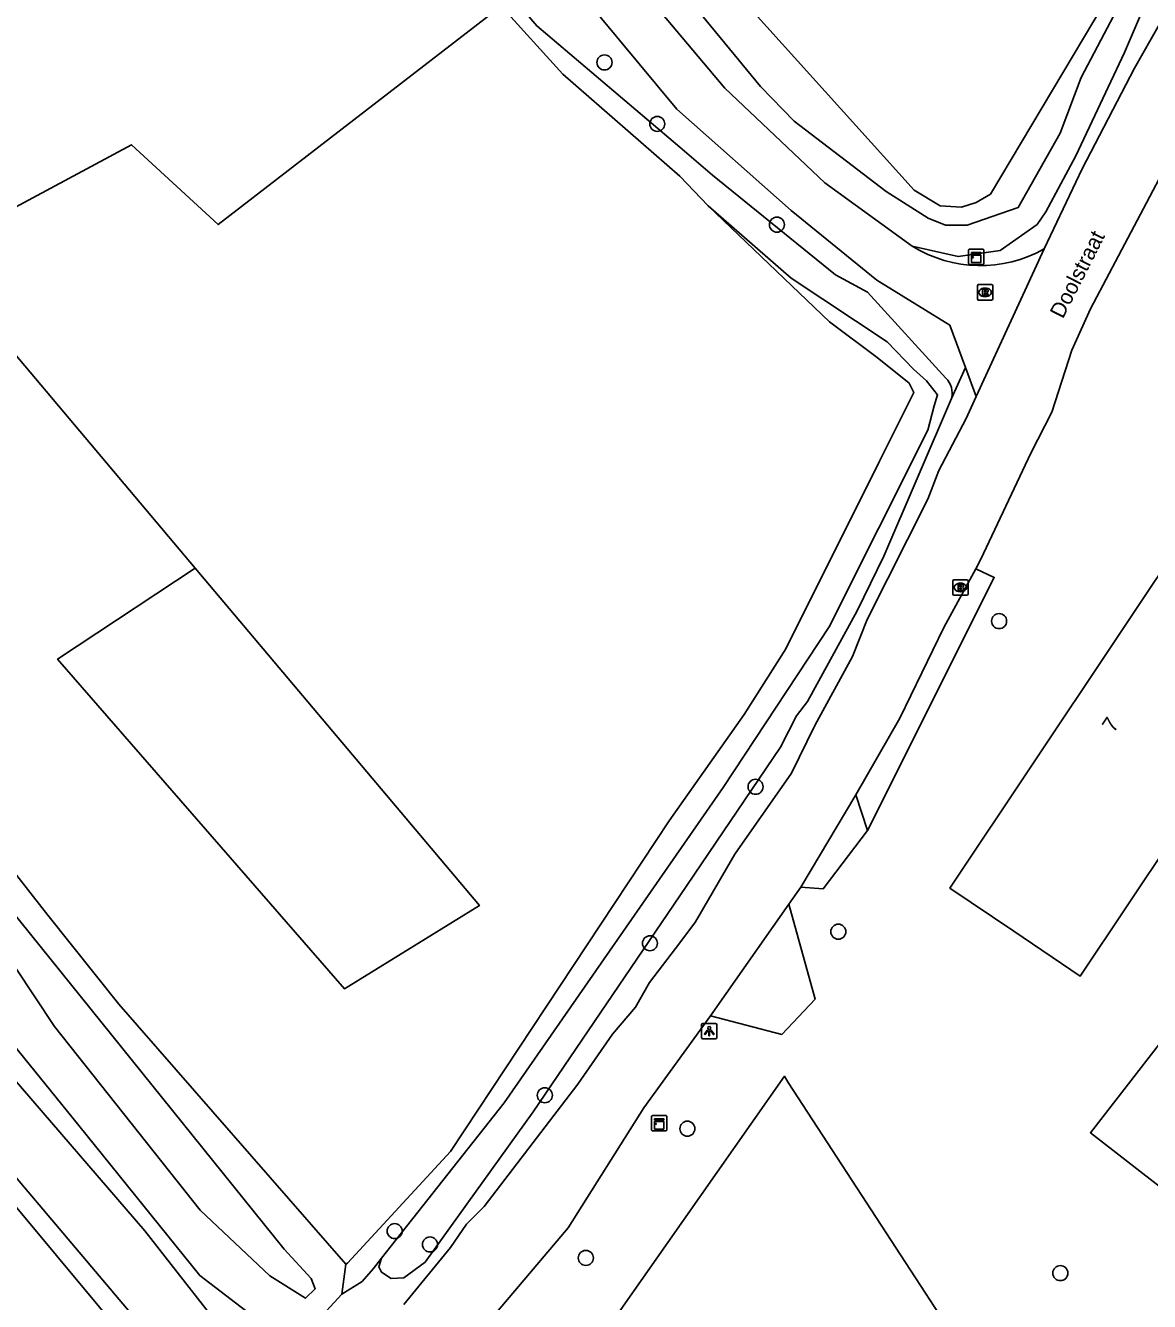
# Model space of a CAD drawing. Extents: x 164494 to 166241, y 382475 to 384494.
# Drawn here: x 164957.5 to 165030.5, y 382904.2 to 382987.1 of the extents above; entities that cross this region are included whole.
import ezdxf

# ---------------------------------------------------------------- set-up
doc = ezdxf.new("R2010")
doc.units = 0
for name, color, linetype in [('IMGEO_Boom', 7, 'Continuous'), ('IMGEO_Brandkraan', 7, 'Continuous'), ('IMGEO_Grasland_agrarisch', 7, 'Continuous'), ('IMGEO_Grasland_overig', 7, 'Continuous'), ('IMGEO_Groenvoorziening', 7, 'Continuous'), ('IMGEO_Hek', 7, 'Continuous'), ('IMGEO_Kast', 7, 'Continuous'), ('IMGEO_Lichtpunt', 7, 'Continuous'), ('IMGEO_Loofbos', 7, 'Continuous'), ('IMGEO_Openbare_ruimte_label', 7, 'Continuous'), ('IMGEO_Pand', 7, 'Continuous'), ('IMGEO_Pand_nummerreeks', 7, 'Continuous'), ('IMGEO_Rijbaan_lokaal_gesloten', 7, 'Continuous'), ('IMGEO_Rioolput', 7, 'Continuous'), ('IMGEO_Spoorbaan_halfverhard', 7, 'Continuous'), ('IMGEO_Voetpad_halfverhard', 7, 'Continuous'), ('IMGEO_Voetpad_open', 7, 'Continuous'), ('IMGEO_Waterloop', 7, 'Continuous')]:
    doc.layers.add(name, color=color, linetype=linetype)

msp = doc.modelspace()

# ---------------------------------------------------------------- linework, layer by layer
at = {"layer": 'IMGEO_Boom'}
for centre in [(164995.114, 382984.685), (164998.544, 382980.686), (165006.318, 382974.144), (165020.759, 382948.382), (165004.933, 382937.617), (165010.31, 382928.2), (164998.067, 382927.448), (164991.235, 382917.57), (165000.5, 382915.4), (164981.477, 382908.747), (164983.774, 382907.877), (164993.9, 382907), (165024.738, 382906.014)]:
    msp.add_circle(centre, 0.489, dxfattribs=at)
at = {"layer": 'IMGEO_Brandkraan'}
for p, q in [((165017.743, 382950.142), (165017.743, 382950.994)), ((165017.818, 382951.068), (165018.67, 382951.068)), ((165018.231, 382950.848), (165018.256, 382950.848)), ((165018.744, 382950.994), (165018.744, 382950.142)), ((165018.67, 382950.068), (165017.818, 382950.068)), ((165018.254, 382950.288), (165018.229, 382950.288))]:
    msp.add_line(p, q, dxfattribs=at)
for points in [[(165017.743, 382950.142), (165017.743, 382950.994)], [(165017.818, 382951.068), (165018.67, 382951.068)], [(165018.091, 382950.768), (165018.091, 382950.368), (165018.304, 382950.368)], [(165018.322, 382950.768), (165018.091, 382950.768)], [(165018.27, 382950.687), (165018.216, 382950.687), (165018.216, 382950.611)], [(165018.744, 382950.994), (165018.744, 382950.142)], [(165018.67, 382950.068), (165017.818, 382950.068)], [(165018.216, 382950.611), (165018.269, 382950.611)], [(165018.278, 382950.535), (165018.216, 382950.535), (165018.216, 382950.454)], [(165018.216, 382950.454), (165018.278, 382950.454)]]:
    msp.add_lwpolyline(points, dxfattribs=at)
for centre, radius, start, end in [((165017.82, 382950.992), 0.0765, 91.55205, 178.44795), ((165017.82, 382950.992), 0.0765, 91.55205, 178.44795), ((165018.271, 382950.649), 0.0379, 267.82845, 90.93552), ((165018.326, 382950.623), 0.145, 59.4692, 91.53667), ((165018.351, 382950.67), 0.0922, 285.51372, 58.15012), ((165018.668, 382950.992), 0.0765, 1.55205, 88.44795), ((165018.668, 382950.992), 0.0765, 1.55205, 88.44795), ((165017.82, 382950.144), 0.0765, 181.55205, 268.44795), ((165017.82, 382950.144), 0.0765, 181.55205, 268.44795), ((165018.279, 382950.494), 0.0404, 269.87594, 90.50774), ((165018.31, 382950.619), 0.251, 268.66757, 293.53466), ((165018.356, 382950.478), 0.105, 301.31148, 78.98903), ((165018.668, 382950.144), 0.0765, 271.55205, 358.44795), ((165018.668, 382950.144), 0.0765, 271.55205, 358.44795)]:
    msp.add_arc(centre, radius, start, end, dxfattribs=at)
for centre, major_axis, ratio, start_param, end_param in [((165018.23, 382950.568), (-0.387, 0.002), 0.722429, 4.712389, 7.853982), ((165018.255, 382950.568), (-0.39, 0.002), 0.717154, 1.570796, 4.712389)]:
    msp.add_ellipse(centre, major_axis=major_axis, ratio=ratio, start_param=start_param, end_param=end_param, dxfattribs=at)
at = {"layer": 'IMGEO_Grasland_agrarisch'}
for points in [[(164978.299, 382906.595), (164963.552, 382923.493), (164958.938, 382929.278), (164948.826, 382942.18), (164906.885, 382991.378), (164906.158, 382994.45), (164904.682, 383001.286), (164903.721, 383005.584), (164901.185, 383009.073), (164869.527, 383048.584)], [(164946.353, 382978.116), (164951.254, 382972.3), (164964.372, 382979.334), (164969.997, 382974.151), (164988.4, 382988.331)], [(164988.369, 382892.566), (164991.283, 382896.514), (164995.872, 382903.225), (165006.822, 382918.809), (165007.043, 382918.399), (165019.128, 382899.871), (165028.021, 382886.396), (165036.892, 382893.976)]]:
    msp.add_lwpolyline(points, dxfattribs=at)
at = {"layer": 'IMGEO_Grasland_overig'}
for points in [[(164942.895, 383066.027), (164962.537, 383037.482), (164965.976, 383039.437), (164978.568, 383020.55), (165001.867, 382991.222), (165015.247, 382976.375), (165016.924, 382975.368), (165018.308, 382975.284), (165019.273, 382975.578), (165020.196, 382976.123), (165027.578, 382988.518)], [(164898.813, 382990.389), (164910.498, 382976.604), (164938.859, 382942.69), (164946.829, 382933.029), (164960.959, 382915.605), (164968.822, 382905.869), (164972.809, 382902.817)], [(164899.832, 382986.626), (164904.636, 382982.112), (164906.784, 382979.696), (164910.292, 382974.365), (164912.186, 382971.704), (164939.554, 382939.216), (164947.607, 382930.826), (164948.628, 382928.172), (164951.201, 382925.02), (164965.239, 382908.759), (164971.547, 382900.696), (164972.697, 382898.76), (164972.933, 382897.454), (164972.645, 382896.417), (164971.752, 382895.263), (164970.343, 382893.802)], [(164968.359, 382896.896), (164968.607, 382897.764), (164968.179, 382898.845), (164955.041, 382914.368), (164945.58, 382926.141), (164944.221, 382929.406), (164942.457, 382931.344), (164939.701, 382932.785), (164937.846, 382934.559), (164931.269, 382942.227), (164910.799, 382966.884), (164905.349, 382974.008), (164903.485, 382977.594), (164901.587, 382979.996), (164900.192, 382981.671)], [(165001.853, 382975.356), (165009.734, 382967.834), (165012.834, 382965.5), (165014.915, 382963.833), (165015.209, 382963.242), (165012.979, 382958.784), (165006.908, 382946.571), (165004.186, 382942.312), (164999.326, 382935.399), (164985.101, 382913.922), (164978.417, 382906.671), (164978.299, 382906.595)], [(164978.048, 382904.646), (164979.355, 382905.468), (164980.096, 382906.311), (164980.625, 382906.982)], [(164978.048, 382904.646), (164978.299, 382906.595)]]:
    msp.add_lwpolyline(points, dxfattribs=at)
at = {"layer": 'IMGEO_Groenvoorziening'}
for points in [[(165017.672, 382962.855), (165018.575, 382964.865)], [(164972.809, 382902.817), (164974.292, 382902.393), (164976.28, 382902.752), (164978.048, 382904.646)]]:
    msp.add_lwpolyline(points, dxfattribs=at)
at = {"layer": 'IMGEO_Hek'}
for points in [[(164749.676, 383168.559), (164783.151, 383128.364), (164821.668, 383082.187), (164846.046, 383053.084), (164878.376, 383014.85), (164897.523, 382991.91), (164898.813, 382990.389), (164910.498, 382976.604), (164938.859, 382942.69), (164946.829, 382933.029), (164960.959, 382915.605), (164968.822, 382905.869), (164972.809, 382902.817), (164977.119, 382899.519), (164973.802, 382896.409), (164970.382, 382893.616)], [(164968.509, 382951.824), (164946.353, 382978.116)], [(164986.985, 382929.9), (164968.509, 382951.824)]]:
    msp.add_lwpolyline(points, dxfattribs=at)
at = {"layer": 'IMGEO_Kast'}
for p, q in [((165018.774, 382971.626), (165018.774, 382972.467)), ((165018.774, 382972.467), (165018.774, 382971.626)), ((165018.849, 382972.551), (165019.69, 382972.551)), ((165019.69, 382972.551), (165018.849, 382972.551)), ((165019.774, 382972.476), (165019.774, 382971.635)), ((165019.774, 382971.635), (165019.774, 382972.476)), ((165019.699, 382971.551), (165018.858, 382971.551)), ((165018.858, 382971.551), (165019.699, 382971.551)), ((164998.169, 382915.328), (164998.169, 382916.169)), ((164998.169, 382916.169), (164998.169, 382915.328)), ((164998.244, 382916.253), (164999.085, 382916.253)), ((164999.085, 382916.253), (164998.244, 382916.253)), ((164999.169, 382916.178), (164999.169, 382915.337)), ((164999.169, 382915.337), (164999.169, 382916.178)), ((164999.094, 382915.253), (164998.253, 382915.253)), ((164998.253, 382915.253), (164999.094, 382915.253))]:
    msp.add_line(p, q, dxfattribs=at)
for points in [[(165018.969, 382972.341), (165019.569, 382972.341), (165019.569, 382972.256), (165018.969, 382972.256), (165018.969, 382972.341)], [(165018.969, 382972.166), (165019.569, 382972.166), (165019.569, 382971.677), (165018.969, 382971.677), (165018.969, 382972.166)], [(164998.364, 382916.043), (164998.964, 382916.043), (164998.964, 382915.958), (164998.364, 382915.958), (164998.364, 382916.043)], [(164998.364, 382915.868), (164998.964, 382915.868), (164998.964, 382915.379), (164998.364, 382915.379), (164998.364, 382915.868)]]:
    msp.add_lwpolyline(points, dxfattribs=at)
for centre in [(165019.053, 382972.015), (164998.448, 382915.717)]:
    msp.add_circle(centre, 0.0377, dxfattribs=at)
for centre, start, end in [((165018.852, 382972.473), 92.4484, 184.28452), ((165018.852, 382972.473), 92.4484, 184.28452), ((165019.696, 382972.473), 2.4484, 94.28452), ((165019.696, 382972.473), 2.4484, 94.28452), ((165018.852, 382971.629), 182.4484, 274.28452), ((165018.852, 382971.629), 182.4484, 274.28452), ((165019.696, 382971.629), 272.4484, 4.28452), ((165019.696, 382971.629), 272.4484, 4.28452), ((164998.247, 382916.175), 92.4484, 184.28452), ((164998.247, 382916.175), 92.4484, 184.28452), ((164999.091, 382916.175), 2.4484, 94.28452), ((164999.091, 382916.175), 2.4484, 94.28452), ((164998.247, 382915.331), 182.4484, 274.28452), ((164998.247, 382915.331), 182.4484, 274.28452), ((164999.091, 382915.331), 272.4484, 4.28452), ((164999.091, 382915.331), 272.4484, 4.28452)]:
    msp.add_arc(centre, 0.0779, start, end, dxfattribs=at)
at = {"layer": 'IMGEO_Lichtpunt'}
for p, q in [((165001.421, 382922.141), (165001.421, 382921.334)), ((165001.421, 382922.141), (165001.421, 382921.334)), ((165002.323, 382922.236), (165001.515, 382922.236)), ((165002.323, 382922.236), (165001.515, 382922.236)), ((165002.417, 382921.334), (165002.417, 382922.141)), ((165002.417, 382921.334), (165002.417, 382922.141)), ((165001.515, 382921.24), (165002.323, 382921.24)), ((165001.515, 382921.24), (165002.323, 382921.24))]:
    msp.add_line(p, q, dxfattribs=at)
for points in [[(165001.795, 382921.805), (165001.834, 382921.777), (165001.646, 382921.515), (165001.608, 382921.542), (165001.795, 382921.805)], [(165001.897, 382921.757), (165001.944, 382921.757), (165001.944, 382921.435), (165001.897, 382921.435), (165001.897, 382921.757)], [(165002.007, 382921.777), (165002.045, 382921.804), (165002.232, 382921.542), (165002.193, 382921.514), (165002.007, 382921.777)]]:
    msp.add_lwpolyline(points, dxfattribs=at)
msp.add_circle((165001.92, 382921.939), 0.0994, dxfattribs=at)
for centre, start, end in [((165001.515, 382922.141), 90, 180), ((165001.515, 382922.141), 90, 180), ((165002.323, 382922.141), 0, 90), ((165002.323, 382922.141), 0, 90), ((165001.515, 382921.334), 180, 270), ((165001.515, 382921.334), 180, 270), ((165002.323, 382921.334), 270, 0), ((165002.323, 382921.334), 270, 360)]:
    msp.add_arc(centre, 0.0946, start, end, dxfattribs=at)
at = {"layer": 'IMGEO_Loofbos'}
msp.add_lwpolyline([(164968.509, 382951.824), (164959.569, 382945.916), (164978.227, 382924.485), (164986.985, 382929.9), (164968.509, 382951.824)], dxfattribs=at)
at = {"layer": 'IMGEO_Pand'}
for points in [[(165036.5, 382941.001), (165042.164, 382949.483), (165037.843, 382952.403), (165033.699, 382955.202), (165017.563, 382931.037), (165021.707, 382928.238), (165026.028, 382925.318), (165032.038, 382934.319), (165035, 382932.341), (165039.462, 382939.024), (165036.5, 382941.001)], [(165045.238, 382915.346), (165047.431, 382918.172), (165035.967, 382927.086), (165026.692, 382915.135), (165033.966, 382909.479), (165041.045, 382918.601), (165045.238, 382915.346)]]:
    msp.add_lwpolyline(points, dxfattribs=at)
at = {"layer": 'IMGEO_Rijbaan_lokaal_gesloten'}
for points in [[(165023.682, 382972.564), (165026.15, 382977.763), (165029.565, 382984.303), (165031.181, 382987.173), (165031.885, 382988.24)], [(165035.21, 382984.79), (165026.7, 382968.663), (165025.486, 382965.99), (165024.184, 382961.958), (165022.83, 382959.286), (165019.573, 382952.406), (165019.24, 382951.789)], [(165019.27, 382962.984), (165023.682, 382972.564)], [(164982.067, 382903.966), (164985.101, 382907.689), (164986.149, 382909.203), (164987.294, 382910.336), (164993.376, 382918.301), (164995.633, 382921.547), (164997.122, 382923.299), (164998.03, 382924.893), (165000, 382927.482), (165001.03, 382928.836), (165003.594, 382933.24), (165007.261, 382938.498), (165008.778, 382941.609), (165011.241, 382946.074), (165012.194, 382948.488), (165016.136, 382956.304), (165016.846, 382958.16), (165018.624, 382961.546), (165019.27, 382962.984)], [(165019.24, 382951.789), (165017.17, 382947.96), (165014.298, 382942.077), (165011.453, 382937.089)], [(165007.863, 382931.089), (165011.453, 382937.089)], [(165007.863, 382931.089), (165007.102, 382929.984)], [(165001.996, 382922.741), (165007.102, 382929.984)], [(165001.996, 382922.741), (164997.666, 382916.757), (164992.742, 382908.964), (164985.682, 382900.629)]]:
    msp.add_lwpolyline(points, dxfattribs=at)
at = {"layer": 'IMGEO_Rioolput'}
for p, q in [((165019.345, 382969.318), (165019.345, 382970.17)), ((165019.42, 382970.244), (165020.272, 382970.244)), ((165019.833, 382970.024), (165019.858, 382970.024)), ((165020.346, 382970.17), (165020.346, 382969.318)), ((165020.272, 382969.244), (165019.42, 382969.244)), ((165019.856, 382969.464), (165019.831, 382969.464))]:
    msp.add_line(p, q, dxfattribs=at)
for points in [[(165019.345, 382969.318), (165019.345, 382970.17)], [(165019.42, 382970.244), (165020.272, 382970.244)], [(165019.934, 382969.942), (165019.682, 382969.944), (165019.682, 382969.544)], [(165019.682, 382969.544), (165019.806, 382969.544), (165019.806, 382969.706), (165019.817, 382969.706)], [(165019.86, 382969.863), (165019.806, 382969.863), (165019.806, 382969.782)], [(165019.806, 382969.782), (165019.858, 382969.782)], [(165020.346, 382970.17), (165020.346, 382969.318)], [(165020.272, 382969.244), (165019.42, 382969.244)], [(165019.864, 382969.677), (165019.935, 382969.544), (165020.075, 382969.544), (165020.01, 382969.67)]]:
    msp.add_lwpolyline(points, dxfattribs=at)
for centre, radius, start, end in [((165019.422, 382970.168), 0.0765, 91.55205, 178.44795), ((165019.422, 382970.168), 0.0765, 91.55205, 178.44795), ((165019.816, 382969.653), 0.0533, 26.02933, 88.69889), ((165019.842, 382969.971), 0.19, 274.7715, 282.96867), ((165019.866, 382969.767), 0.0964, 77.00612, 93.18647), ((165019.88, 382969.824), 0.0378, 276.66336, 79.67722), ((165019.933, 382969.832), 0.109, 350.36119, 89.41601), ((165019.931, 382969.832), 0.112, 277.58423, 350.98172), ((165019.915, 382969.617), 0.108, 29.51342, 73.79051), ((165020.27, 382970.168), 0.0765, 1.55205, 88.44795), ((165020.27, 382970.168), 0.0765, 1.55205, 88.44795), ((165019.422, 382969.32), 0.0765, 181.55205, 268.44795), ((165019.422, 382969.32), 0.0765, 181.55205, 268.44795), ((165020.27, 382969.32), 0.0765, 271.55205, 358.44795), ((165020.27, 382969.32), 0.0765, 271.55205, 358.44795)]:
    msp.add_arc(centre, radius, start, end, dxfattribs=at)
for centre, major_axis, ratio, start_param, end_param in [((165019.832, 382969.744), (-0.387, 0.002), 0.722429, 4.712389, 7.853982), ((165019.857, 382969.744), (-0.39, 0.002), 0.717154, 1.570796, 4.712389)]:
    msp.add_ellipse(centre, major_axis=major_axis, ratio=ratio, start_param=start_param, end_param=end_param, dxfattribs=at)
at = {"layer": 'IMGEO_Spoorbaan_halfverhard'}
msp.add_lwpolyline([(164967.998, 382896.954), (164945.283, 382924.214), (164944.503, 382925.573), (164943.311, 382928.98), (164942.635, 382929.878), (164941.692, 382930.579), (164940.005, 382931.34), (164938.436, 382932.404), (164936.991, 382934.036), (164905.067, 382972.47), (164902.647, 382975.555), (164901.062, 382979.118)], dxfattribs=at)
at = {"layer": 'IMGEO_Voetpad_halfverhard'}
for points in [[(165015.116, 382972.749), (165009.429, 382976.853), (165002.924, 382983.02), (164995.304, 382992.08), (164983.764, 383006.976), (164976.307, 383014.726), (164975.747, 383015.453)], [(164974.637, 383009.542), (164981.184, 383005.457), (164993.635, 382989.092), (164999.815, 382981.64), (165007.238, 382975.053), (165012.813, 382970.534), (165017.56, 382967.611), (165018.575, 382964.865)], [(165018.575, 382964.865), (165019.27, 382962.984)], [(165012.213, 382934.776), (165020.443, 382951.217), (165019.24, 382951.789)]]:
    msp.add_lwpolyline(points, dxfattribs=at)
msp.add_arc((165019.555, 382979.879), 8.399, 238.09319, 299.43236, dxfattribs=at)
at = {"layer": 'IMGEO_Voetpad_open'}
for points in [[(165011.453, 382937.089), (165012.213, 382934.776)], [(165012.213, 382934.776), (165009.333, 382930.99), (165007.863, 382931.089)], [(165007.102, 382929.984), (165008.811, 382923.808), (165006.645, 382921.521), (165001.996, 382922.741)]]:
    msp.add_lwpolyline(points, dxfattribs=at)
at = {"layer": 'IMGEO_Waterloop'}
for points in [[(164973.357, 382905.838), (164975.678, 382904.378), (164976.315, 382904.997), (164976.046, 382905.669), (164974.307, 382907.57), (164952.503, 382934.608), (164905.519, 382989.733), (164904.31, 382994.399), (164902.22, 383004.055), (164867.646, 383047.751)], [(165028.222, 382987.725), (165026.086, 382983.698), (165024.724, 382980.091), (165021.998, 382975.247), (165018.674, 382974.106), (165017.274, 382974.114), (165016.158, 382974.56), (165013.428, 382976.295), (165007.435, 382980.868), (165005.249, 382983.12), (165000, 382989.514), (164990.786, 383000), (164985.246, 383006.707), (164979.731, 383014.456), (164978.086, 383017.145), (164975.747, 383015.453)], [(165017.299, 382964.177), (165012.212, 382969.763), (165010.119, 382970.888), (165002.138, 382977.359), (165000, 382979.175), (164990.716, 382987.061), (164989.425, 382988.568), (164981.443, 383000), (164975.758, 383008.141)], [(164901.074, 383000.85), (164902.13, 382996.956), (164902.607, 382994.593), (164902.741, 382991.356), (164902.199, 382990.505), (164901.444, 382989.962), (164902.983, 382988.908), (164907.363, 382983.718), (164924.18, 382964.132), (164950.416, 382933.566), (164954.193, 382929.818), (164959.362, 382922.044), (164968.829, 382910.103), (164973.357, 382905.838)], [(164988.4, 382988.331), (164992.399, 382983.912), (165000, 382977.286), (165001.853, 382975.356)], [(165028.73, 382988.684), (165029.536, 382988.299), (165030.019, 382987.907), (165028.915, 382985.327), (165025.735, 382978.625), (165023.796, 382974.977), (165023.232, 382974.16), (165020.824, 382972.474), (165018.088, 382972.069), (165015.116, 382972.749)], [(165001.853, 382975.356), (165007.243, 382970.671), (165013.474, 382966.537), (165015.202, 382964.763), (165016.048, 382964.005), (165016.761, 382963.095), (165016.533, 382962.376), (165016.119, 382960.789), (165009.708, 382948.007), (165002.824, 382937.566), (164988.585, 382917.085), (164980.625, 382906.982)], [(164980.625, 382906.982), (164980.451, 382906.431), (164980.615, 382906.068), (164981.249, 382905.672), (164982.067, 382905.708), (164983.461, 382906.729), (164990.487, 382916.497), (165000, 382930.534), (165006.551, 382940.201), (165007.582, 382942.235), (165008.306, 382943.151), (165011.538, 382949.052), (165013.257, 382952.601), (165017.672, 382962.855)]]:
    msp.add_lwpolyline(points, dxfattribs=at)
msp.add_arc((165016.313, 382963.185), 1.398, 346.33974, 45.1729, dxfattribs=at)

# ---------------------------------------------------------------- texts
at = {"layer": 'IMGEO_Openbare_ruimte_label'}
msp.add_text('Doolstraat', height=1, rotation=63.07637, dxfattribs=at).set_placement((165024.9, 382967.981))
at = {"layer": 'IMGEO_Pand_nummerreeks'}
msp.add_text('7', height=1, rotation=56.26446, dxfattribs=at).set_placement((165028.206, 382941.069))

doc.saveas('drawing.dxf')
